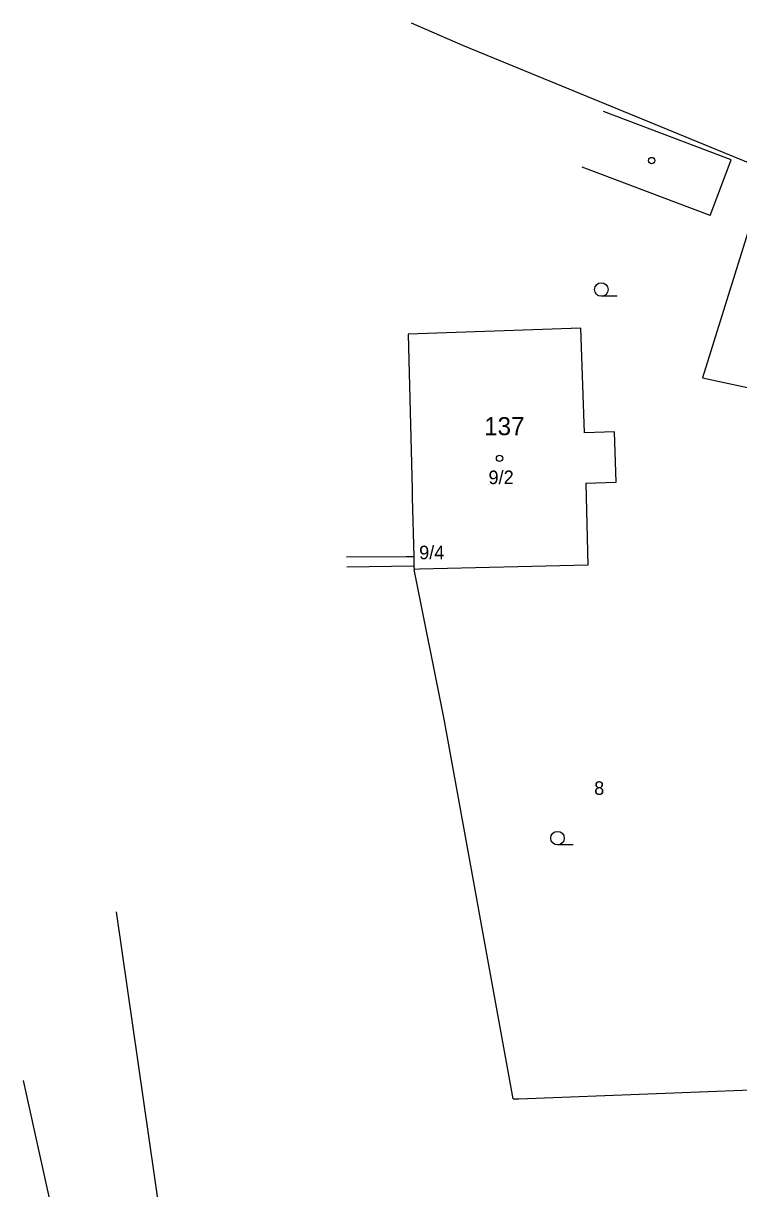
# Model space of a CAD drawing. Extents: x -836739 to -835945, y -1070775 to -1070126.
# Drawn here: x -836729.7 to -836690.1, y -1070440 to -1070375.4 of the extents above; entities that cross this region are included whole.
import ezdxf

# ---------------------------------------------------------------- set-up
doc = ezdxf.new("R2010")
doc.units = 0
for name, color, linetype in [('BodPole_mer', 7, 'Continuous'), ('Budovy_hranice', 7, 'Continuous'), ('Budovy_kody', 7, 'Continuous'), ('Doprava_hranice', 7, 'Continuous'), ('OstPloch_kody', 7, 'Continuous'), ('RuianAdr_popis', 7, 'Continuous'), ('RuianPar_popis', 7, 'Continuous'), ('Stavby_hr_zed', 7, 'Continuous'), ('Stavby_linie', 7, 'Continuous')]:
    doc.layers.add(name, color=color, linetype=linetype)

msp = doc.modelspace()

# ---------------------------------------------------------------- linework, layer by layer
at = {"layer": 'BodPole_mer'}
for p, q in [((-836690.52, -1070383.01), (-836690.52, -1070383.01)), ((-836691.69, -1070386.08), (-836691.69, -1070386.08)), ((-836698.84, -1070392.32), (-836698.84, -1070392.32)), ((-836692.11, -1070395.08), (-836692.11, -1070395.08)), ((-836698.64, -1070398.12), (-836698.64, -1070398.12)), ((-836696.98, -1070398.06), (-836696.98, -1070398.06)), ((-836698.57, -1070400.9), (-836698.57, -1070400.9)), ((-836696.89, -1070400.86), (-836696.89, -1070400.86)), ((-836708.09, -1070404.98), (-836708.09, -1070404.98)), ((-836708.08, -1070405.49), (-836708.08, -1070405.49)), ((-836698.46, -1070405.44), (-836698.46, -1070405.44)), ((-836708.07, -1070405.68), (-836708.07, -1070405.68)), ((-836707.77, -1070405.67), (-836707.77, -1070405.67)), ((-836706.4, -1070413.97), (-836706.4, -1070413.97)), ((-836702.58, -1070435.01), (-836702.58, -1070435.01)), ((-836702.27, -1070435), (-836702.27, -1070435))]:
    msp.add_line(p, q, dxfattribs=at)
at = {"layer": 'Budovy_hranice'}
for p, q in [((-836690.52, -1070383.01), (-836697.58, -1070380.33)), ((-836691.69, -1070386.08), (-836698.76, -1070383.4)), ((-836691.69, -1070386.08), (-836690.52, -1070383.01)), ((-836698.84, -1070392.32), (-836708.4, -1070392.65)), ((-836698.64, -1070398.12), (-836698.84, -1070392.32)), ((-836696.98, -1070398.06), (-836698.64, -1070398.12)), ((-836696.89, -1070400.86), (-836696.98, -1070398.06)), ((-836698.57, -1070400.9), (-836696.89, -1070400.86)), ((-836698.57, -1070400.9), (-836698.46, -1070405.44))]:
    msp.add_line(p, q, dxfattribs=at)
for points in [[(-836688.94, -1070395.76), (-836685.66, -1070384.65), (-836688.53, -1070383.6), (-836692.11, -1070395.08), (-836688.94, -1070395.76)], [(-836708.4, -1070392.65), (-836708.18, -1070401.25), (-836708.17, -1070401.7), (-836708.09, -1070404.98), (-836708.08, -1070405.49), (-836708.07, -1070405.68)], [(-836698.46, -1070405.44), (-836707.77, -1070405.67), (-836708.07, -1070405.68)]]:
    msp.add_lwpolyline(points, dxfattribs=at)
at = {"layer": 'Budovy_kody'}
for centre in [(-836694.92, -1070383.04), (-836703.34, -1070399.53)]:
    msp.add_circle(centre, 0.175, dxfattribs=at)
at = {"layer": 'Doprava_hranice'}
for p, q in [((-836720.08, -1070455.51), (-836724.54, -1070424.65)), ((-836729.7, -1070433.98), (-836727.6, -1070443.53))]:
    msp.add_line(p, q, dxfattribs=at)
at = {"layer": 'OstPloch_kody'}
for p, q in [((-836696.835, -1070390.56), (-836697.71, -1070390.56)), ((-836699.255, -1070420.94), (-836700.13, -1070420.94))]:
    msp.add_line(p, q, dxfattribs=at)
for centre in [(-836697.71, -1070390.185), (-836700.13, -1070420.565)]:
    msp.add_ellipse(centre, major_axis=(0.375, 0), ratio=0.999999, dxfattribs=at)
at = {"layer": 'RuianAdr_popis'}
msp.add_line((-836704.19, -1070398.25), (-836704.19, -1070398.25), dxfattribs=at)
at = {"layer": 'RuianPar_popis'}
for p, q in [((-836703.95, -1070400.96), (-836703.95, -1070400.96)), ((-836707.79, -1070405.12), (-836707.79, -1070405.12)), ((-836698.1, -1070418.17), (-836698.1, -1070418.17))]:
    msp.add_line(p, q, dxfattribs=at)
at = {"layer": 'Stavby_hr_zed'}
msp.add_line((-836711.8, -1070405.54), (-836708.08, -1070405.49), dxfattribs=at)
msp.add_lwpolyline([(-836708.09, -1070404.98), (-836708.5, -1070404.99), (-836711.81, -1070405.01)], dxfattribs=at)
at = {"layer": 'Stavby_linie'}
for points in [[(-836688.53, -1070383.6), (-836705.37, -1070376.67), (-836708.22, -1070375.44)], [(-836702.58, -1070435.01), (-836706.4, -1070413.97), (-836708.07, -1070405.68)], [(-836702.58, -1070435.01), (-836702.27, -1070435), (-836687.04, -1070434.42)]]:
    msp.add_lwpolyline(points, dxfattribs=at)

# ---------------------------------------------------------------- texts
at = {"layer": 'RuianAdr_popis'}
msp.add_text('137', height=1, dxfattribs=at).set_placement((-836704.19, -1070398.25))
at = {"layer": 'RuianPar_popis'}
for s, p in [('9/2', (-836703.95, -1070400.96)), ('9/4', (-836707.79, -1070405.12)), ('8', (-836698.1, -1070418.17))]:
    msp.add_text(s, height=0.75, dxfattribs=at).set_placement(p)

doc.saveas('drawing.dxf')
